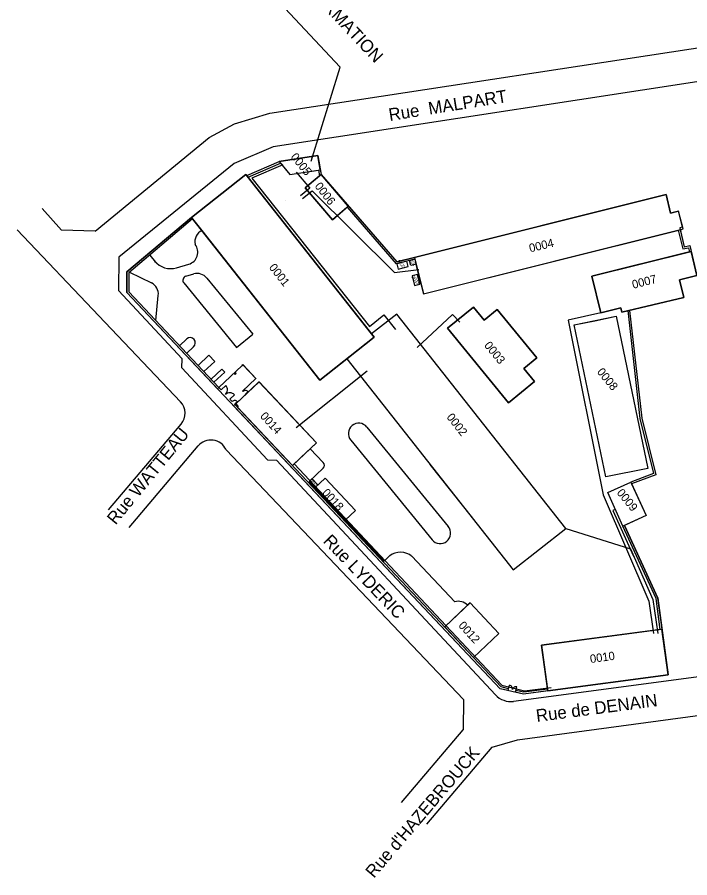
# Model space of a CAD drawing. Extents: x 703432 to 707394, y 7057985 to 7059523.
# Drawn here: x 703819.8 to 703980.5, y 7058347.3 to 7058552.7 of the extents above; entities that cross this region are included whole.
import ezdxf

# ---------------------------------------------------------------- set-up
doc = ezdxf.new("R2010")
doc.units = 0
for name, color, linetype in [('DH_HACHURE-MOTIF', 7, 'Continuous'), ('DH_TEXTE', 7, 'Continuous'), ('GEOSID_AIRE_AMENAGEE_POLYGONE', 7, 'Continuous'), ('GO_DALLE', 7, 'Continuous'), ('GO_MUR_EXTERIEUR', 7, 'Continuous'), ('IMM_LIMITE PHYSIQUE', 7, 'Continuous'), ('R_ELEC_BT_60HZ_LIAISON_CL_B', 7, 'Continuous'), ('R_PLU_CANALISATION_CL_A', 7, 'Continuous'), ('RES_INCENDIE - EQUIP - TEXTE', 7, 'Continuous'), ('SID_NUMERO_BATI', 7, 'Continuous'), ('SID_POLYLIGNES_BATI', 7, 'Continuous'), ('SID_POLYLIGNES_IMMEUBLE', 7, 'Continuous'), ('VOIRIE_BORDURE', 7, 'Continuous'), ('VOIRIE_ROUTE', 7, 'Continuous')]:
    doc.layers.add(name, color=color, linetype=linetype)

msp = doc.modelspace()

# ---------------------------------------------------------------- linework, layer by layer
at = {"layer": 'DH_HACHURE-MOTIF'}
for p, q in [((703892.04, 7058514.89), (703892.42, 7058515.22)), ((703892.42, 7058515.22), (703898.92, 7058507.62)), ((703888.62, 7058511.97), (703892.04, 7058514.89)), ((703895.12, 7058504.37), (703888.62, 7058511.97)), ((703952.91, 7058479.32), (703957.82, 7058480.28)), ((703960.45, 7058442.99), (703952.91, 7058479.32)), ((703970.47, 7058445.01), (703960.45, 7058442.99)), ((703960.94, 7058439.23), (703966.47, 7058441.73)), ((703964.55, 7058431.25), (703960.94, 7058439.23)), ((703970.08, 7058433.75), (703964.55, 7058431.25))]:
    msp.add_line(p, q, dxfattribs=at)
for points in [[(703891.79, 7058516.22), (703892.24, 7058516.3), (703891.66, 7058519.75), (703882.39, 7058518.32), (703882.72, 7058517.92), (703884.94, 7058515.2), (703891.79, 7058516.22)], [(703861.71, 7058504.57), (703863.91, 7058501.78), (703892.09, 7058466.06), (703898.57, 7058471.17), (703905.13, 7058476.34), (703904.51, 7058477.13), (703874.77, 7058514.82), (703874.46, 7058515.21), (703861.43, 7058504.92), (703861.71, 7058504.57)], [(703914.82, 7058494.96), (703915.1, 7058493.82), (703916.89, 7058486.66), (703978.54, 7058502.07), (703978.98, 7058502.18), (703977.83, 7058506.46), (703975.89, 7058505.98), (703974.86, 7058510.43), (703937.99, 7058501.21), (703914.71, 7058495.4), (703914.82, 7058494.96)], [(703898.92, 7058507.62), (703898.58, 7058507.33), (703895.12, 7058504.37)], [(703964.09, 7058483.38), (703964.33, 7058482.31), (703979.08, 7058485.8), (703978.08, 7058490.02), (703982.22, 7058491.05), (703980.89, 7058496.84), (703980.46, 7058496.73), (703957.11, 7058490.9), (703959.3, 7058482.16), (703964.09, 7058483.38)], [(703912.93, 7058494.49), (703910.55, 7058493.89), (703910.87, 7058492.6), (703913.25, 7058493.2), (703912.93, 7058494.49)], [(703914.76, 7058488.65), (703916.05, 7058488.97), (703915.45, 7058491.35), (703914.16, 7058491.02), (703914.76, 7058488.65)], [(703931.38, 7058480.45), (703928.85, 7058483.54), (703922.66, 7058478.47), (703937.24, 7058460.68), (703943.43, 7058465.75), (703940.89, 7058468.84), (703943.98, 7058471.38), (703934.48, 7058482.98), (703931.38, 7058480.45)], [(703950.89, 7058430.69), (703910.51, 7058481.87), (703904.51, 7058477.13), (703905.13, 7058476.34), (703898.57, 7058471.17), (703938.33, 7058420.78), (703950.89, 7058430.69)], [(703957.82, 7058480.28), (703962.93, 7058481.34), (703970.47, 7058445.01)], [(703890.33, 7058442.49), (703890.26, 7058442.56), (703889.54, 7058441.88), (703890.96, 7058440.37), (703891.68, 7058441.06), (703890.33, 7058442.49)], [(703966.47, 7058441.73), (703966.56, 7058441.54), (703970.08, 7058433.75)], [(703927.45, 7058412.34), (703921.98, 7058407.19), (703928.85, 7058399.91), (703934.89, 7058405.62), (703928.03, 7058412.89), (703927.45, 7058412.34)], [(703946.54, 7058392.34), (703946.6, 7058391.89), (703975.34, 7058395.75), (703973.88, 7058406.65), (703973.43, 7058406.59), (703945.13, 7058402.79), (703946.54, 7058392.34)]]:
    msp.add_lwpolyline(points, dxfattribs=at)
for points in [[(703887.58, 7058447.59), (703891.3, 7058451.1), (703877.58, 7058465.65), (703872.06, 7058460.45), (703872.64, 7058459.83), (703872.47, 7058459.67), (703885.62, 7058445.74)], [(703893.41, 7058442.68), (703890.96, 7058440.37), (703898.2, 7058432.7), (703900.65, 7058435.01)]]:
    msp.add_lwpolyline(points, close=True, dxfattribs=at)
at = {"layer": 'GEOSID_AIRE_AMENAGEE_POLYGONE'}
msp.add_lwpolyline([(703913.84, 7058493.5), (703913.56, 7058494.64), (703914.81, 7058494.96), (703915.1, 7058493.82)], close=True, dxfattribs=at)
at = {"layer": 'GO_DALLE'}
msp.add_lwpolyline([(703914.82, 7058494.96), (703915.1, 7058493.82), (703913.84, 7058493.5), (703913.56, 7058494.64)], close=True, dxfattribs=at)
at = {"layer": 'GO_MUR_EXTERIEUR'}
for p, q in [((703891.66, 7058519.75), (703882.39, 7058518.32)), ((703892.24, 7058516.3), (703891.66, 7058519.75)), ((703882.39, 7058518.32), (703884.94, 7058515.2)), ((703861.43, 7058504.92), (703874.46, 7058515.21)), ((703874.46, 7058515.21), (703905.13, 7058476.34)), ((703884.94, 7058515.2), (703892.24, 7058516.3)), ((703892.42, 7058515.22), (703888.62, 7058511.97)), ((703898.92, 7058507.62), (703892.42, 7058515.22)), ((703888.62, 7058511.97), (703895.12, 7058504.37)), ((703888.62, 7058511.97), (703888.62, 7058511.97)), ((703974.86, 7058510.43), (703914.71, 7058495.4)), ((703975.89, 7058505.98), (703974.86, 7058510.43)), ((703895.12, 7058504.37), (703898.92, 7058507.62)), ((703892.09, 7058466.06), (703861.43, 7058504.92)), ((703977.83, 7058506.46), (703975.89, 7058505.98)), ((703978.98, 7058502.18), (703977.83, 7058506.46)), ((703916.89, 7058486.66), (703978.98, 7058502.18)), ((703957.11, 7058490.9), (703980.89, 7058496.84)), ((703914.71, 7058495.4), (703916.89, 7058486.66)), ((703959.3, 7058482.16), (703957.11, 7058490.9)), ((703982.22, 7058491.05), (703978.08, 7058490.02)), ((703978.08, 7058490.02), (703979.08, 7058485.8)), ((703922.66, 7058478.47), (703928.85, 7058483.54)), ((703928.85, 7058483.54), (703931.38, 7058480.45)), ((703931.38, 7058480.45), (703934.48, 7058482.98)), ((703934.48, 7058482.98), (703943.98, 7058471.38)), ((703910.51, 7058481.87), (703904.51, 7058477.13)), ((703950.89, 7058430.69), (703910.51, 7058481.87)), ((703952.91, 7058479.32), (703962.93, 7058481.34)), ((703962.93, 7058481.34), (703970.47, 7058445.01)), ((703937.24, 7058460.68), (703922.66, 7058478.47)), ((703960.45, 7058442.99), (703952.91, 7058479.32)), ((703905.13, 7058476.34), (703892.09, 7058466.06)), ((703905.13, 7058476.34), (703898.57, 7058471.17)), ((703904.51, 7058477.13), (703905.13, 7058476.34)), ((703898.57, 7058471.17), (703938.33, 7058420.78)), ((703943.98, 7058471.38), (703940.89, 7058468.84)), ((703940.89, 7058468.84), (703943.43, 7058465.75)), ((703877.61, 7058465.69), (703872.06, 7058460.45)), ((703891.34, 7058451.14), (703877.61, 7058465.69)), ((703943.43, 7058465.75), (703937.24, 7058460.68)), ((703885.62, 7058445.74), (703891.34, 7058451.14)), ((703970.47, 7058445.01), (703960.45, 7058442.99)), ((703889.54, 7058441.88), (703890.26, 7058442.56)), ((703890.96, 7058440.37), (703889.54, 7058441.88)), ((703890.26, 7058442.56), (703891.68, 7058441.06)), ((703891.68, 7058441.06), (703890.96, 7058440.37)), ((703960.94, 7058439.23), (703966.47, 7058441.73)), ((703966.47, 7058441.73), (703970.08, 7058433.75)), ((703964.55, 7058431.25), (703960.94, 7058439.23)), ((703970.08, 7058433.75), (703964.55, 7058431.25)), ((703938.33, 7058420.78), (703950.89, 7058430.69)), ((703921.98, 7058407.19), (703928.03, 7058412.89)), ((703928.03, 7058412.89), (703934.89, 7058405.62)), ((703928.85, 7058399.91), (703921.98, 7058407.19)), ((703945.13, 7058402.79), (703973.88, 7058406.65)), ((703973.88, 7058406.65), (703975.34, 7058395.75)), ((703934.89, 7058405.62), (703928.85, 7058399.91)), ((703946.6, 7058391.89), (703945.13, 7058402.79)), ((703975.34, 7058395.75), (703946.6, 7058391.89))]:
    msp.add_line(p, q, dxfattribs=at)
for points in [[(703910.55, 7058493.89), (703910.87, 7058492.6), (703913.25, 7058493.2), (703912.93, 7058494.49)], [(703915.45, 7058491.35), (703914.16, 7058491.02), (703914.76, 7058488.65), (703916.05, 7058488.97)], [(703893.41, 7058442.68), (703900.65, 7058435.01), (703898.2, 7058432.7), (703890.96, 7058440.37)]]:
    msp.add_lwpolyline(points, close=True, dxfattribs=at)
for points in [[(703979.08, 7058485.8), (703964.33, 7058482.31), (703964.09, 7058483.38), (703959.3, 7058482.16)], [(703872.06, 7058460.45), (703872.64, 7058459.83), (703872.47, 7058459.67), (703885.62, 7058445.74)]]:
    msp.add_lwpolyline(points, dxfattribs=at)
at = {"layer": 'IMM_LIMITE PHYSIQUE'}
for p, q in [((703874.68, 7058514.95), (703882.41, 7058518.28)), ((703874.98, 7058514.59), (703882.71, 7058517.92)), ((703891.79, 7058516.22), (703892.02, 7058514.88)), ((703892.24, 7058516.3), (703892.42, 7058515.22)), ((703898.63, 7058507.37), (703910.37, 7058493.84)), ((703898.97, 7058507.66), (703910.52, 7058494.35)), ((703861.44, 7058504.92), (703846.01, 7058491.95)), ((703861.72, 7058504.57), (703846.46, 7058491.74)), ((703914.83, 7058494.96), (703910.37, 7058493.84)), ((703914.71, 7058495.4), (703910.52, 7058494.35)), ((703846.01, 7058491.95), (703846.01, 7058487)), ((703846.46, 7058491.74), (703846.46, 7058487.2)), ((703846.01, 7058487), (703867.68, 7058464.03)), ((703846.48, 7058487.16), (703868.01, 7058464.33)), ((703868.01, 7058464.33), (703873.57, 7058469.58)), ((703873.66, 7058463.45), (703876.87, 7058466.48)), ((703868.01, 7058464.33), (703867.68, 7058464.03)), ((703868.01, 7058464.33), (703868.56, 7058463.75)), ((703868.56, 7058463.75), (703869.65, 7058464.78)), ((703870.62, 7058461.57), (703871.71, 7058462.6)), ((703870.62, 7058461.57), (703871.17, 7058460.98)), ((703873.66, 7058463.45), (703873.71, 7058463.38)), ((703874.99, 7058463.35), (703874.33, 7058462.73)), ((703874.33, 7058462.73), (703874.39, 7058462.67)), ((703871.85, 7058460.26), (703871.52, 7058459.96)), ((703871.52, 7058459.96), (703935.22, 7058392.43)), ((703872.44, 7058460.95), (703871.79, 7058460.33)), ((703871.79, 7058460.33), (703871.85, 7058460.26)), ((703871.85, 7058460.26), (703935.45, 7058392.84)), ((703937.15, 7058391.98), (703935.22, 7058392.43)), ((703937.25, 7058392.42), (703935.45, 7058392.84)), ((703937.15, 7058391.98), (703937.45, 7058393.27)), ((703938.9, 7058391.57), (703939.2, 7058392.86)), ((703940.85, 7058391.57), (703939, 7058392.01)), ((703946.6, 7058391.89), (703940.83, 7058391.12)), ((703946.54, 7058392.34), (703940.85, 7058391.57)), ((703940.83, 7058391.12), (703938.9, 7058391.57))]:
    msp.add_line(p, q, dxfattribs=at)
for points in [[(703977.79, 7058501.89), (703978.84, 7058497.41), (703980.24, 7058497.68), (703980.45, 7058496.74)], [(703978.23, 7058501.99), (703979.18, 7058497.94), (703980.58, 7058498.21), (703980.89, 7058496.84)], [(703965.71, 7058482.69), (703968.63, 7058456.97), (703971.86, 7058443.8), (703966.48, 7058441.74)], [(703966.16, 7058482.74), (703969.08, 7058457.05), (703972.39, 7058443.52), (703966.64, 7058441.32)], [(703973.49, 7058406.59), (703972.46, 7058413.94), (703964.56, 7058431.22)], [(703973.94, 7058406.66), (703972.9, 7058414.07), (703964.97, 7058431.41)]]:
    msp.add_lwpolyline(points, dxfattribs=at)
for points in [[(703871.69, 7058467.67), (703871.9, 7058467.45), (703872.14, 7058467.68), (703871.94, 7058467.9)], [(703873.73, 7058469.73), (703873.49, 7058469.68), (703873.65, 7058469.49)], [(703873.73, 7058469.73), (703876.89, 7058466.38), (703876.93, 7058466.41), (703873.77, 7058469.76)]]:
    msp.add_lwpolyline(points, close=True, dxfattribs=at)
for centre, radius, start, end in [((703868.56, 7058463.75), 1.5, 313.3307, 43.3307), ((703874.33, 7058462.73), 0.9, 43.3307, 133.3307), ((703870.62, 7058461.57), 1.5, 43.3307, 133.3307), ((703871.79, 7058460.33), 0.9, 43.3307, 133.3307), ((703937.28, 7058392.41), 0.874, 346.7916, 78.7098), ((703938.98, 7058392.01), 0.874, 75.2683, 166.7916)]:
    msp.add_arc(centre, radius, start, end, dxfattribs=at)
at = {"layer": 'R_ELEC_BT_60HZ_LIAISON_CL_B'}
for p, q in [((703896.95, 7058540.81), (703864.53, 7058575.54)), ((703890.03, 7058518.34), (703896.95, 7058540.81)), ((703959.3, 7058482.16), (703951.47, 7058480.44)), ((703951.47, 7058480.44), (703959.8, 7058438.72)), ((703886.5, 7058454.75), (703903.42, 7058468.34))]:
    msp.add_line(p, q, dxfattribs=at)
for points in [[(703883.3, 7058517.51), (703875.86, 7058514.35), (703903.97, 7058478.9), (703907.44, 7058481.65), (703910.19, 7058478.18)], [(703886.5, 7058515.77), (703889.7, 7058511.92), (703887.51, 7058510.1)], [(703888.01, 7058509.44), (703890.26, 7058511.27), (703909.97, 7058491.8), (703915.75, 7058492.52)], [(703925.55, 7058479.93), (703923.84, 7058481.77), (703915.42, 7058473.91)], [(703886, 7058446.1), (703935.6, 7058393.29), (703941.03, 7058391.92), (703947.44, 7058392.74)], [(703959.8, 7058438.72), (703970.77, 7058413.31), (703971.85, 7058405.63)], [(703962.74, 7058435.24), (703962.16, 7058435.01), (703967.08, 7058424.09)], [(703950.89, 7058430.69), (703966.33, 7058425.83), (703971.74, 7058413.71), (703972.88, 7058405.62)]]:
    msp.add_lwpolyline(points, dxfattribs=at)
at = {"layer": 'R_PLU_CANALISATION_CL_A'}
msp.add_line((703918.45, 7058445.98), (703928.57, 7058433.15), dxfattribs=at)
at = {"layer": 'RES_INCENDIE - EQUIP - TEXTE'}
msp.add_line((703883.81, 7058509), (703883.81, 7058509), dxfattribs=at)
at = {"layer": 'SID_POLYLIGNES_BATI'}
for p, q in [((703891.66, 7058519.75), (703882.39, 7058518.32)), ((703892.24, 7058516.3), (703891.66, 7058519.75)), ((703882.39, 7058518.32), (703884.94, 7058515.2)), ((703861.43, 7058504.92), (703874.46, 7058515.21)), ((703874.46, 7058515.21), (703905.13, 7058476.34)), ((703884.94, 7058515.2), (703892.24, 7058516.3)), ((703892.42, 7058515.22), (703888.62, 7058511.97)), ((703898.92, 7058507.62), (703892.42, 7058515.22)), ((703888.62, 7058511.97), (703895.12, 7058504.37)), ((703888.62, 7058511.97), (703888.62, 7058511.97)), ((703974.86, 7058510.43), (703914.71, 7058495.4)), ((703975.89, 7058505.98), (703974.86, 7058510.43)), ((703895.12, 7058504.37), (703898.92, 7058507.62)), ((703892.09, 7058466.06), (703861.43, 7058504.92)), ((703977.83, 7058506.46), (703975.89, 7058505.98)), ((703978.98, 7058502.18), (703977.83, 7058506.46)), ((703916.89, 7058486.66), (703978.98, 7058502.18)), ((703914.71, 7058495.4), (703916.89, 7058486.66)), ((703922.66, 7058478.47), (703928.85, 7058483.54)), ((703928.85, 7058483.54), (703931.38, 7058480.45)), ((703931.38, 7058480.45), (703934.48, 7058482.98)), ((703934.48, 7058482.98), (703943.98, 7058471.38)), ((703910.51, 7058481.87), (703904.51, 7058477.13)), ((703950.89, 7058430.69), (703910.51, 7058481.87)), ((703952.91, 7058479.32), (703962.93, 7058481.34)), ((703962.93, 7058481.34), (703970.47, 7058445.01)), ((703937.24, 7058460.68), (703922.66, 7058478.47)), ((703960.45, 7058442.99), (703952.91, 7058479.32)), ((703905.13, 7058476.34), (703892.09, 7058466.06)), ((703905.13, 7058476.34), (703898.57, 7058471.17)), ((703904.51, 7058477.13), (703905.13, 7058476.34)), ((703898.57, 7058471.17), (703938.33, 7058420.78)), ((703943.98, 7058471.38), (703940.89, 7058468.84)), ((703940.89, 7058468.84), (703943.43, 7058465.75)), ((703943.43, 7058465.75), (703937.24, 7058460.68)), ((703877.58, 7058465.65), (703872.06, 7058460.45)), ((703891.3, 7058451.1), (703877.58, 7058465.65)), ((703885.62, 7058445.74), (703891.3, 7058451.1)), ((703970.47, 7058445.01), (703960.45, 7058442.99)), ((703889.54, 7058441.88), (703890.26, 7058442.56)), ((703890.96, 7058440.37), (703889.54, 7058441.88)), ((703890.26, 7058442.56), (703891.68, 7058441.06)), ((703891.68, 7058441.06), (703890.96, 7058440.37)), ((703960.94, 7058439.23), (703966.47, 7058441.73)), ((703966.47, 7058441.73), (703970.08, 7058433.75)), ((703964.55, 7058431.25), (703960.94, 7058439.23)), ((703970.08, 7058433.75), (703964.55, 7058431.25)), ((703938.33, 7058420.78), (703950.89, 7058430.69)), ((703921.98, 7058407.19), (703928.03, 7058412.89)), ((703928.03, 7058412.89), (703934.89, 7058405.62)), ((703928.85, 7058399.91), (703921.98, 7058407.19)), ((703945.13, 7058402.79), (703973.88, 7058406.65)), ((703973.88, 7058406.65), (703975.34, 7058395.75)), ((703934.89, 7058405.62), (703928.85, 7058399.91)), ((703946.6, 7058391.89), (703945.13, 7058402.79)), ((703975.34, 7058395.75), (703946.6, 7058391.89))]:
    msp.add_line(p, q, dxfattribs=at)
for points in [[(703910.55, 7058493.89), (703910.87, 7058492.6), (703913.25, 7058493.2), (703912.93, 7058494.49)], [(703913.84, 7058493.5), (703913.56, 7058494.64), (703914.82, 7058494.96), (703915.1, 7058493.82)], [(703915.45, 7058491.35), (703914.16, 7058491.02), (703914.76, 7058488.65), (703916.05, 7058488.97)], [(703893.41, 7058442.68), (703900.65, 7058435.01), (703898.2, 7058432.7), (703890.96, 7058440.37)]]:
    msp.add_lwpolyline(points, close=True, dxfattribs=at)
msp.add_lwpolyline([(703872.06, 7058460.45), (703872.64, 7058459.83), (703872.47, 7058459.67), (703885.62, 7058445.74)], dxfattribs=at)
at = {"layer": 'SID_POLYLIGNES_IMMEUBLE'}
for p, q in [((703910.52, 7058494.35), (703974.86, 7058510.43)), ((703974.86, 7058510.43), (703975.89, 7058505.98)), ((703975.89, 7058505.98), (703977.79, 7058506.46)), ((703910.52, 7058494.35), (703910.52, 7058494.35)), ((703846.01, 7058487), (703846.01, 7058491.95)), ((703982.22, 7058491.05), (703978.08, 7058490.02)), ((703978.08, 7058490.02), (703979.08, 7058485.8)), ((703935.22, 7058392.43), (703846.01, 7058487)), ((703979.08, 7058485.8), (703966.16, 7058482.75)), ((703972.39, 7058443.52), (703966.64, 7058441.32)), ((703966.64, 7058441.32), (703970.08, 7058433.75)), ((703970.08, 7058433.75), (703964.97, 7058431.41)), ((703964.97, 7058431.41), (703972.9, 7058414.07)), ((703972.9, 7058414.07), (703975.34, 7058395.75))]:
    msp.add_line(p, q, dxfattribs=at)
for points in [[(703874.46, 7058515.21), (703874.68, 7058514.95), (703882.41, 7058518.28), (703882.39, 7058518.32), (703891.66, 7058519.75)], [(703891.66, 7058519.75), (703892.42, 7058515.22), (703910.52, 7058494.35)], [(703846.01, 7058491.95), (703861.43, 7058504.92), (703874.46, 7058515.21)], [(703977.79, 7058506.46), (703978.69, 7058502.62), (703978.12, 7058502.47), (703979.18, 7058497.94), (703980.58, 7058498.21), (703982.22, 7058491.05)], [(703966.16, 7058482.75), (703969.08, 7058457.05), (703972.39, 7058443.52)], [(703975.34, 7058395.75), (703940.83, 7058391.12), (703935.22, 7058392.43)]]:
    msp.add_lwpolyline(points, dxfattribs=at)
at = {"layer": 'VOIRIE_BORDURE'}
for p, q in [((703851.47, 7058495.95), (703852.89, 7058494.22)), ((703857.15, 7058492.7), (703857.15, 7058492.7)), ((703857.89, 7058492.92), (703860.81, 7058493.77)), ((703846.65, 7058491.9), (703851.87, 7058489.33)), ((703860.11, 7058490.9), (703861.99, 7058491.44)), ((703865.15, 7058490.47), (703876.11, 7058477.08)), ((703859.63, 7058489.32), (703872.24, 7058473.91)), ((703852.93, 7058480.32), (703853.53, 7058486.34)), ((703858.59, 7058474.31), (703860.33, 7058475.95)), ((703872.24, 7058473.91), (703876.11, 7058477.08)), ((703860.31, 7058472.5), (703861.96, 7058474.06)), ((703863.05, 7058469.59), (703865.63, 7058472.02)), ((703867.01, 7058470.57), (703865.63, 7058472.02)), ((703864.42, 7058468.13), (703867.01, 7058470.57)), ((703866.14, 7058466.31), (703868.72, 7058468.75)), ((703866.83, 7058465.59), (703869.41, 7058468.02)), ((703869.41, 7058468.02), (703868.72, 7058468.75)), ((703903.37, 7058454.9), (703922.82, 7058431.16)), ((703899.5, 7058451.73), (703918.95, 7058427.99)), ((703889.84, 7058449.73), (703892.93, 7058446.46)), ((703892.89, 7058445.04), (703889.54, 7058441.88)), ((703889.54, 7058441.88), (703907.47, 7058422.87)), ((703907.47, 7058422.87), (703908.86, 7058424.19)), ((703914.09, 7058424.03), (703924.36, 7058413.14))]:
    msp.add_line(p, q, dxfattribs=at)
for centre, radius, start, end in [((703865.26, 7058499.14), 3, 115.4761, 192.4737), ((703859.97, 7058496.65), 3, 286.3025, 37.942), ((703856.49, 7058497.72), 5, 219.5679, 286.3025), ((703860.39, 7058489.94), 1, 106.0656, 219.3307), ((703862.82, 7058488.56), 3, 39.3307, 106.0656), ((703850.54, 7058486.63), 3, 354.3306, 63.7442), ((703861.12, 7058474.99), 1.25, 312.1096, 129.3307), ((703901.43, 7058453.31), 2.5, 39.3307, 219.3307), ((703892.21, 7058445.77), 1, 313.3306, 43.3306), ((703920.88, 7058429.57), 2.5, 219.3307, 39.3307), ((703925.27, 7058410.29), 3, 43.3308, 107.6513)]:
    msp.add_arc(centre, radius, start, end, dxfattribs=at)
msp.add_ellipse((703911.39, 7058422), major_axis=(-3.68, 0), ratio=0.816097, start_param=3.897855, end_param=5.468654, dxfattribs=at)
at = {"layer": 'VOIRIE_ROUTE'}
for p, q in [((703858.84, 7058460.92), (703819.81, 7058501.99)), ((703838.44, 7058501.65), (703830.42, 7058501.86)), ((703844.06, 7058495.43), (703844.02, 7058487.48)), ((703844.02, 7058487.48), (703859.19, 7058471.22)), ((703859.13, 7058469.02), (703859.19, 7058471.22)), ((703859.13, 7058469.02), (703879.59, 7058447.09)), ((703841.61, 7058435.11), (703858.99, 7058455.58)), ((703846.54, 7058430.93), (703863.04, 7058450.37)), ((703926.42, 7058389.83), (703869.71, 7058449.49)), ((703879.59, 7058447.09), (703881.83, 7058447.02)), ((703881.78, 7058447.02), (703934.1, 7058390.95)), ((703926.42, 7058389.83), (703926.39, 7058382.61)), ((703911.65, 7058365.24), (703926.39, 7058382.61))]:
    msp.add_line(p, q, dxfattribs=at)
for points in [[(703838.44, 7058501.65), (703865.67, 7058524.02), (703871.7, 7058527.31), (703880.16, 7058529.85), (703997.05, 7058547.69)], [(703998.3, 7058539.81), (703881.01, 7058521.77), (703871.65, 7058517.81), (703844.06, 7058495.43)], [(703830.42, 7058501.86), (703825.75, 7058507.09)], [(703938.42, 7058389.41), (703991.62, 7058396.55)], [(703917.73, 7058360.09), (703933.28, 7058378.43), (703939.34, 7058380.24), (703991.86, 7058387.29)]]:
    msp.add_lwpolyline(points, dxfattribs=at)
for centre, radius, start, end in [((703855.94, 7058458.17), 4, 319.6675, 43.547), ((703866.09, 7058447.79), 4, 25.2763, 139.6675), ((703937.76, 7058394.36), 5, 223.0213, 277.6524)]:
    msp.add_arc(centre, radius, start, end, dxfattribs=at)

# ---------------------------------------------------------------- texts
at = {"layer": 'DH_TEXTE'}
for s, rotation, p in [('Rue  MALPART', 9.1668, (703908.83, 7058527.94)), ('Rue WATTEAU', 50.7423, (703843.32, 7058431.38)), ('Rue LYDERIC', 313.8024, (703892.72, 7058427.51)), ('Rue de DENAIN', 7.4746, (703943.99, 7058384.46)), ("Rue d'HAZEBROUCK", 49.6268, (703905.04, 7058347.03))]:
    msp.add_text(s, height=3, rotation=rotation, dxfattribs=at).set_placement(p)
at = {"layer": 'R_ELEC_BT_60HZ_LIAISON_CL_B'}
msp.add_text('POSTE DE TRANSFORMATION', height=3, rotation=313.0213, dxfattribs=at).set_placement((703865.04, 7058584.79))
at = {"layer": 'SID_NUMERO_BATI'}
for s, height, rotation, p in [('0005', 2, 309.3307, (703885.02, 7058519.33)), ('0006', 2, 307.9879, (703890.78, 7058512.36)), ('0004', 2, 13.5243, (703942.4, 7058496.59)), ('0020', 0.738, 308.0308, (703910.64, 7058494.48)), ('0021', 0.702, 308.0308, (703913.25, 7058494.94)), ('0001', 2, 308.2727, (703879.85, 7058492.96)), ('0019', 0.866, 308.0308, (703913.94, 7058490.73)), ('0007', 2, 14.5051, (703967.02, 7058487.89)), ('0003', 2, 309.3307, (703931.28, 7058474.33)), ('0008', 2, 309.3307, (703958.23, 7058468.01)), ('0014', 2, 312.5129, (703877.72, 7058457.38)), ('0002', 2, 308.2727, (703922.3, 7058457.21)), ('0013', 0.698, 312.5129, (703889.58, 7058442.06)), ('0018', 2, 312.5129, (703892.53, 7058439.08)), ('0009', 2, 309.3307, (703962.95, 7058439.15)), ('0012', 2, 312.5129, (703925.1, 7058407.4)), ('0010', 2, 8.0003, (703956.83, 7058398.53))]:
    msp.add_text(s, height=height, rotation=rotation, dxfattribs=at).set_placement(p)

doc.saveas('drawing.dxf')
